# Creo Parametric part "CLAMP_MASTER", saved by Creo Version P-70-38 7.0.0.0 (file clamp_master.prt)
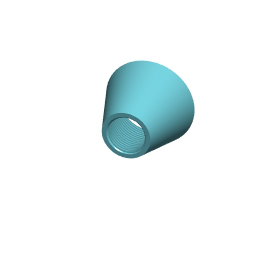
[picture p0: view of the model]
Units: millimeter Kilogram Sec (mmKs); MM, KILOGRAM, SECS
Materials in the file: PP

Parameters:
  PTC_MATERIAL_NAME = "PP"
  GRANTA_DATALINK_VERSION = "5"
  GRANTA_DATABASE_KEY = "Granta_Typical_Materials"
  GRANTA_IDENTITY_GUID = "ff860c73-d74d-48d2-a9b6-5ced973d81f3"
  GRANTA_VERSION_GUID = "0e93ee24-01f8-4558-b835-9833d1fcc101"
  GRANTA_MODEL_REFERENCE = "00000000-0000-0000-0000-000000000000"

Created from: XX_INLBS_PART_SOLID_ABS.PRT

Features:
  1. datum plane "RIGHT"
  2. datum plane "TOP"
  3. datum plane "FRONT"
  4. coordinate system
  5. sketch "Sketch 1"
  6. sketch "Sketch 2", "A_3"
  7. sketch "Sketch 3"
  8. revolve "Revolve 1"
  9. chamfer "Chamfer 1"
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
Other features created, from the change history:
  group "COPIED_GROUP"
  cut "Volume Helical Sweep 1" (2 times)
  extruded cut "Extrude 1" (2 times)
  feature "Split Out Body 1" (2 times)
  chamfer "Chamfer 2" (4 times)
  feature "Split Body 1" (4 times)
  round "Round 1"

Other named items: PIECE1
